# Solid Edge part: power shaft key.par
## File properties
Author: vinurabandara
Template: iso metric part.par
Last saved by: vinurabandara
Revision: 6
Application: Solid Edge
Accuracy: 0.990
Username: Nimesh.N
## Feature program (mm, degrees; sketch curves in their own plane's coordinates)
sketch for "unnamed Protrusion 1" plane through (0, 0, 0) normal (0, -1, 0) x-axis (1, 0, 0)
  line (-22, -9) -> (22, -9)
  arc centre (22, -4) radius 5 from (22, -9) to (27, -4) ccw
  line (27, -4) -> (27, 4)
  arc centre (22, 4) radius 5 from (22, 9) to (27, 4) cw
  line (22, 9) -> (-22, 9)
  arc centre (-22, 4) radius 5 from (-22, 9) to (-27, 4) ccw
  line (-27, 4) -> (-27, -4)
  arc centre (-22, -4) radius 5 from (-27, -4) to (-22, -9) ccw
  dimension (linear) = 27
  dimension (linear) = 22
extrude "unnamed Protrusion 1" add finite 11 along +normal
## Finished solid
Body 1: solid body, 10 faces, 24 edges, 16 vertices.
  Faces by surface: plane 6, cylinder 4
  Edges by curve: line 16, circle 8
Bounding box of the edges (mm): 54.000 x 11.000 x 18.000, from (-27, -11, -9) to (27, 0, 9).
Cylindrical faces by radius (mm): R5 x4
Planar faces by outward normal: +x 1, +y 1, +z 1, -x 1, -y 1, -z 1
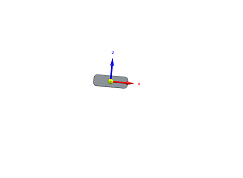
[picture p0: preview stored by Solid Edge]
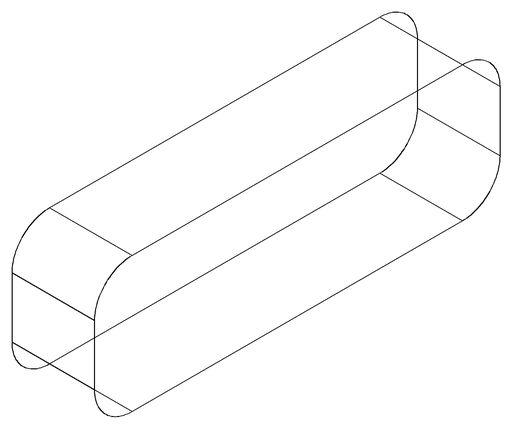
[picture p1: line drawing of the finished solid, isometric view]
